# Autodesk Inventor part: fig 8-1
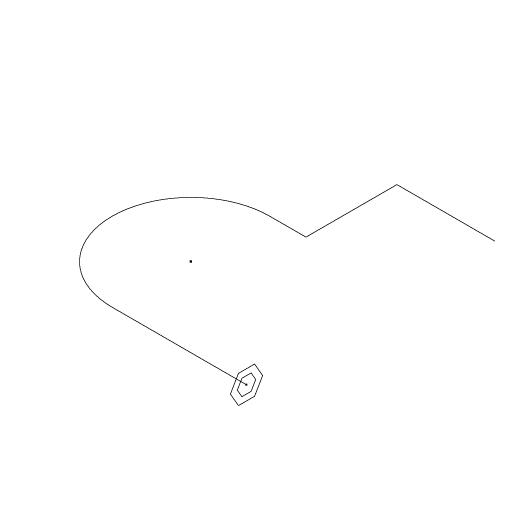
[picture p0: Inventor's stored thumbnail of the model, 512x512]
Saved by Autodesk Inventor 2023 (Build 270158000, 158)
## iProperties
Created: 2004-05
Part Number: fig 8-1
Document SubType Name: Modeling
Designer: CADCIM Technologies
Manufacturer: Standard
Standards Organization: Custom
Density: 1 g/cm^3
Material: Generic
Appearance: Default
Author: CADCIM Technologies
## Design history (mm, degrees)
sketch "Sketch1"
  geometry: L1 (-42.583, 3.219)-(-90.066, 3.219); L2 (-90.066, 58.92)-(-77.282, 58.92); L3 (-77.282, 58.92)-(-77.282, 91.063); L4 (-77.282, 91.063)-(-42.583, 91.063); A1 r 27.851 centre (-90.066, 31.07) between (-90.066, 58.92) and (-90.066, 3.219)
  constraints: 8 end point, 2 parallel, 2 point on circle, 2 tangent, 1 centre point, 1 perpendicular
workplane "Work Plane2"
sketch "Sketch2"
  geometry: L1 (-5.697, 0)-(-2.849, 4.934); L2 (-2.849, 4.934)-(2.849, 4.934); L3 (2.849, 4.934)-(5.697, 0); L4 (5.697, 0)-(2.849, -4.934); L5 (2.849, -4.934)-(-2.849, -4.934); L6 (-2.849, -4.934)-(-5.697, 0); L7 (-3.256, 0)-(-1.628, 2.819); L8 (-1.628, 2.819)-(1.628, 2.819); L9 (1.628, 2.819)-(3.256, 0); L10 (3.256, 0)-(1.628, -2.819); L11 (1.628, -2.819)-(-1.628, -2.819); L12 (-1.628, -2.819)-(-3.256, 0); 2 further points
  constraints: 24 end point, 1 coincident, 22 other
